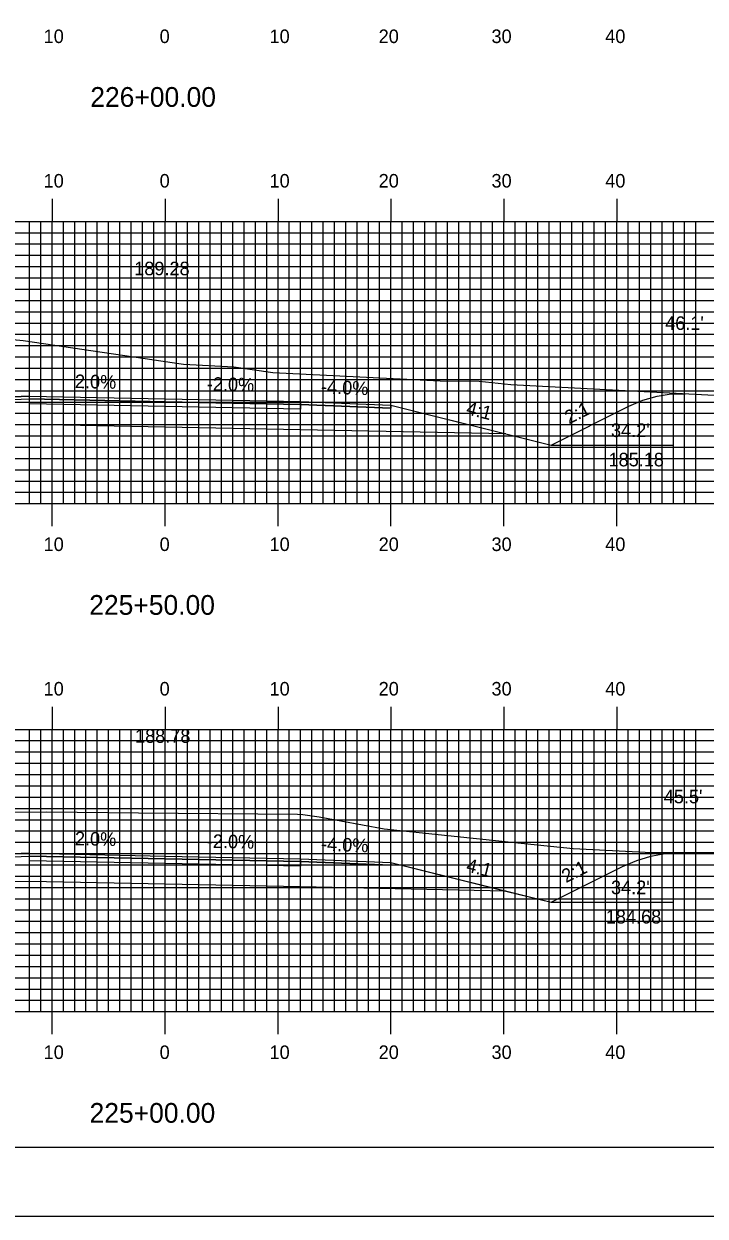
# Model space of a CAD drawing. Extents: x 1798388 to 1798731, y 442591 to 442811.
# Drawn here: x 1798541 to 1798601.3, y 442590.5 to 442696.2 of the extents above; entities that cross this region are included whole.
import ezdxf

# ---------------------------------------------------------------- set-up
doc = ezdxf.new("R2010")
doc.units = 0
for name, color, linetype in [('ANNOTATION', 7, 'Continuous'), ('BORDER', 7, 'Continuous'), ('D_Roadway_Centerline', 7, 'Continuous'), ('D_Roadway_Centerline_Text', 7, 'Continuous'), ('D_Roadway_Edge_Shoulder', 7, 'Continuous'), ('D_Roadway_Edge_TW', 7, 'Continuous'), ('D_Roadway_Pavement', 7, 'Continuous'), ('D_Roadway_SlopeLines', 7, 'Continuous'), ('D_Roadway_SubGrade', 7, 'Continuous'), ('D_Text_Standard', 7, 'Continuous'), ('H_V ANNOTATION', 7, 'Continuous'), ('MAJOR', 7, 'Continuous'), ('MINOR', 7, 'Continuous'), ('PDRAIN', 7, 'Continuous'), ('PLOT BOUNDARY', 7, 'Continuous'), ('S_Roadway_Centerline', 7, 'Continuous')]:
    doc.layers.add(name, color=color, linetype=linetype)

msp = doc.modelspace()

# ---------------------------------------------------------------- linework, layer by layer
at = {"layer": 'BORDER'}
msp.add_lwpolyline([(1798403.87, 442596.67), (1798723.87, 442596.67), (1798723.87, 442806.67), (1798403.87, 442806.67)], close=True, dxfattribs=at)
at = {"layer": 'D_Roadway_Centerline'}
for points in [[(1798501.26, 442666.86), (1798502.51, 442666.89), (1798503.76, 442666.72), (1798505.01, 442666.37), (1798506.26, 442665.84), (1798519.3, 442659.33), (1798523.3, 442660.33), (1798533.47, 442662.87), (1798541.47, 442663.19), (1798553.47, 442662.95), (1798565.47, 442662.71), (1798573.47, 442662.39), (1798583.64, 442659.85), (1798587.64, 442658.85), (1798594.53, 442662.29), (1798595.78, 442662.83), (1798597.03, 442663.19), (1798598.28, 442663.39), (1798599.53, 442663.41)], [(1798502.18, 442626.07), (1798503.43, 442626.02), (1798504.68, 442625.8), (1798505.93, 442625.43), (1798507.18, 442624.88), (1798519.3, 442618.83), (1798523.3, 442619.83), (1798533.47, 442622.37), (1798541.47, 442622.69), (1798553.47, 442622.45), (1798565.47, 442622.21), (1798573.47, 442621.89), (1798583.64, 442619.35), (1798587.64, 442618.35), (1798593.98, 442621.51), (1798595.23, 442622.06), (1798596.48, 442622.45), (1798597.73, 442622.68), (1798598.98, 442622.75)]]:
    msp.add_lwpolyline(points, dxfattribs=at)
at = {"layer": 'D_Roadway_Edge_Shoulder'}
for points in [[(1798541.47, 442663.19), (1798533.47, 442662.87), (1798533.47, 442662.62), (1798541.47, 442662.94)], [(1798565.47, 442662.71), (1798573.47, 442662.39), (1798573.47, 442662.14), (1798565.47, 442662.46)], [(1798541.47, 442622.69), (1798533.47, 442622.37), (1798533.47, 442622.12), (1798541.47, 442622.44)], [(1798565.47, 442622.21), (1798573.47, 442621.89), (1798573.47, 442621.64), (1798565.47, 442621.96)]]:
    msp.add_lwpolyline(points, close=True, dxfattribs=at)
at = {"layer": 'D_Roadway_Edge_TW'}
for points in [[(1798541.47, 442662.94), (1798541.47, 442663.19), (1798553.47, 442662.95), (1798565.47, 442662.71), (1798565.47, 442662.46), (1798553.47, 442662.7)], [(1798541.47, 442622.44), (1798541.47, 442622.69), (1798553.47, 442622.45), (1798565.47, 442622.21), (1798565.47, 442621.96), (1798553.47, 442622.2)]]:
    msp.add_lwpolyline(points, close=True, dxfattribs=at)
at = {"layer": 'D_Roadway_Pavement'}
for points in [[(1798541.47, 442662.52), (1798541.47, 442662.94), (1798553.47, 442662.7), (1798565.47, 442662.46), (1798565.47, 442662.04), (1798553.47, 442662.28)], [(1798541.47, 442622.02), (1798541.47, 442622.44), (1798553.47, 442622.2), (1798565.47, 442621.96), (1798565.47, 442621.54), (1798553.47, 442621.78)]]:
    msp.add_lwpolyline(points, close=True, dxfattribs=at)
at = {"layer": 'D_Roadway_SlopeLines'}
for points in [[(1798587.64, 442658.85), (1798594.53, 442662.29), (1798595.78, 442662.83), (1798597.03, 442663.19), (1798598.28, 442663.39), (1798599.53, 442663.41)], [(1798573.47, 442662.39), (1798587.64, 442658.85)], [(1798587.64, 442618.35), (1798593.98, 442621.51), (1798595.23, 442622.06), (1798596.48, 442622.45), (1798597.73, 442622.68), (1798598.98, 442622.75)], [(1798573.47, 442621.89), (1798587.64, 442618.35)]]:
    msp.add_lwpolyline(points, dxfattribs=at)
at = {"layer": 'D_Roadway_SubGrade'}
for points in [[(1798541.47, 442660.69), (1798523.3, 442660.33), (1798533.47, 442662.87), (1798533.47, 442662.62), (1798541.47, 442662.94), (1798553.47, 442662.7), (1798565.47, 442662.46), (1798573.47, 442662.14), (1798573.47, 442662.39), (1798583.64, 442659.85), (1798565.47, 442660.21), (1798553.47, 442660.45)], [(1798541.47, 442620.19), (1798523.3, 442619.83), (1798533.47, 442622.37), (1798533.47, 442622.12), (1798541.47, 442622.44), (1798553.47, 442622.2), (1798565.47, 442621.96), (1798573.47, 442621.64), (1798573.47, 442621.89), (1798583.64, 442619.35), (1798565.47, 442619.71), (1798553.47, 442619.95)]]:
    msp.add_lwpolyline(points, close=True, dxfattribs=at)
at = {"layer": 'MAJOR'}
for p, q in [((1798543.47, 442680.67), (1798543.47, 442678.67)), ((1798553.47, 442680.67), (1798553.47, 442678.67)), ((1798563.47, 442680.67), (1798563.47, 442678.67)), ((1798573.47, 442680.67), (1798573.47, 442678.67)), ((1798583.47, 442680.67), (1798583.47, 442678.67)), ((1798593.47, 442680.67), (1798593.47, 442678.67)), ((1798413.47, 442678.67), (1798693.47, 442678.67)), ((1798413.47, 442678.67), (1798693.47, 442678.67)), ((1798543.47, 442653.67), (1798543.47, 442678.67)), ((1798553.47, 442653.67), (1798553.47, 442678.67)), ((1798563.47, 442653.67), (1798563.47, 442678.67)), ((1798573.47, 442653.67), (1798573.47, 442678.67)), ((1798583.47, 442653.67), (1798583.47, 442678.67)), ((1798593.47, 442653.67), (1798593.47, 442678.67)), ((1798413.47, 442673.67), (1798693.47, 442673.67)), ((1798413.47, 442668.67), (1798693.47, 442668.67)), ((1798413.47, 442663.67), (1798693.47, 442663.67)), ((1798413.47, 442658.67), (1798693.47, 442658.67)), ((1798413.47, 442653.67), (1798693.47, 442653.67)), ((1798413.47, 442653.67), (1798693.47, 442653.67)), ((1798543.47, 442651.66), (1798543.47, 442653.67)), ((1798553.47, 442651.66), (1798553.47, 442653.67)), ((1798563.47, 442651.66), (1798563.47, 442653.67)), ((1798573.47, 442651.66), (1798573.47, 442653.67)), ((1798583.47, 442651.66), (1798583.47, 442653.67)), ((1798593.47, 442651.66), (1798593.47, 442653.67)), ((1798543.47, 442635.67), (1798543.47, 442633.67)), ((1798553.47, 442635.67), (1798553.47, 442633.67)), ((1798563.47, 442635.67), (1798563.47, 442633.67)), ((1798573.47, 442635.67), (1798573.47, 442633.67)), ((1798583.47, 442635.67), (1798583.47, 442633.67)), ((1798593.47, 442635.67), (1798593.47, 442633.67)), ((1798413.47, 442633.67), (1798693.47, 442633.67)), ((1798413.47, 442633.67), (1798693.47, 442633.67)), ((1798543.47, 442608.67), (1798543.47, 442633.67)), ((1798553.47, 442608.67), (1798553.47, 442633.67)), ((1798563.47, 442608.67), (1798563.47, 442633.67)), ((1798573.47, 442608.67), (1798573.47, 442633.67)), ((1798583.47, 442608.67), (1798583.47, 442633.67)), ((1798593.47, 442608.67), (1798593.47, 442633.67)), ((1798413.47, 442628.67), (1798693.47, 442628.67)), ((1798413.47, 442623.67), (1798693.47, 442623.67)), ((1798413.47, 442618.67), (1798693.47, 442618.67)), ((1798413.47, 442613.67), (1798693.47, 442613.67)), ((1798413.47, 442608.67), (1798693.47, 442608.67)), ((1798413.47, 442608.67), (1798693.47, 442608.67)), ((1798543.47, 442606.66), (1798543.47, 442608.67)), ((1798553.47, 442606.66), (1798553.47, 442608.67)), ((1798563.47, 442606.66), (1798563.47, 442608.67)), ((1798573.47, 442606.66), (1798573.47, 442608.67)), ((1798583.47, 442606.66), (1798583.47, 442608.67)), ((1798593.47, 442606.66), (1798593.47, 442608.67))]:
    msp.add_line(p, q, dxfattribs=at)
at = {"layer": 'MINOR'}
for p, q in [((1798541.47, 442653.67), (1798541.47, 442678.67)), ((1798542.47, 442653.67), (1798542.47, 442678.67)), ((1798544.47, 442653.67), (1798544.47, 442678.67)), ((1798545.47, 442653.67), (1798545.47, 442678.67)), ((1798546.47, 442653.67), (1798546.47, 442678.67)), ((1798547.47, 442653.67), (1798547.47, 442678.67)), ((1798548.47, 442653.67), (1798548.47, 442678.67)), ((1798549.47, 442653.67), (1798549.47, 442678.67)), ((1798550.47, 442653.67), (1798550.47, 442678.67)), ((1798551.47, 442653.67), (1798551.47, 442678.67)), ((1798552.47, 442653.67), (1798552.47, 442678.67)), ((1798554.47, 442653.67), (1798554.47, 442678.67)), ((1798555.47, 442653.67), (1798555.47, 442678.67)), ((1798556.47, 442653.67), (1798556.47, 442678.67)), ((1798557.47, 442653.67), (1798557.47, 442678.67)), ((1798558.47, 442653.67), (1798558.47, 442678.67)), ((1798559.47, 442653.67), (1798559.47, 442678.67)), ((1798560.47, 442653.67), (1798560.47, 442678.67)), ((1798561.47, 442653.67), (1798561.47, 442678.67)), ((1798562.47, 442653.67), (1798562.47, 442678.67)), ((1798564.47, 442653.67), (1798564.47, 442678.67)), ((1798565.47, 442653.67), (1798565.47, 442678.67)), ((1798566.47, 442653.67), (1798566.47, 442678.67)), ((1798567.47, 442653.67), (1798567.47, 442678.67)), ((1798568.47, 442653.67), (1798568.47, 442678.67)), ((1798569.47, 442653.67), (1798569.47, 442678.67)), ((1798570.47, 442653.67), (1798570.47, 442678.67)), ((1798571.47, 442653.67), (1798571.47, 442678.67)), ((1798572.47, 442653.67), (1798572.47, 442678.67)), ((1798574.47, 442653.67), (1798574.47, 442678.67)), ((1798575.47, 442653.67), (1798575.47, 442678.67)), ((1798576.47, 442653.67), (1798576.47, 442678.67)), ((1798577.47, 442653.67), (1798577.47, 442678.67)), ((1798578.47, 442653.67), (1798578.47, 442678.67)), ((1798579.47, 442653.67), (1798579.47, 442678.67)), ((1798580.47, 442653.67), (1798580.47, 442678.67)), ((1798581.47, 442653.67), (1798581.47, 442678.67)), ((1798582.47, 442653.67), (1798582.47, 442678.67)), ((1798584.47, 442653.67), (1798584.47, 442678.67)), ((1798585.47, 442653.67), (1798585.47, 442678.67)), ((1798586.47, 442653.67), (1798586.47, 442678.67)), ((1798587.47, 442653.67), (1798587.47, 442678.67)), ((1798588.47, 442653.67), (1798588.47, 442678.67)), ((1798589.47, 442653.67), (1798589.47, 442678.67)), ((1798590.47, 442653.67), (1798590.47, 442678.67)), ((1798591.47, 442653.67), (1798591.47, 442678.67)), ((1798592.47, 442653.67), (1798592.47, 442678.67)), ((1798594.47, 442653.67), (1798594.47, 442678.67)), ((1798595.47, 442653.67), (1798595.47, 442678.67)), ((1798596.47, 442653.67), (1798596.47, 442678.67)), ((1798597.47, 442653.67), (1798597.47, 442678.67)), ((1798598.47, 442653.67), (1798598.47, 442678.67)), ((1798599.47, 442653.67), (1798599.47, 442678.67)), ((1798600.47, 442653.67), (1798600.47, 442678.67)), ((1798413.47, 442677.67), (1798693.47, 442677.67)), ((1798413.47, 442676.67), (1798693.47, 442676.67)), ((1798413.47, 442675.67), (1798693.47, 442675.67)), ((1798413.47, 442674.67), (1798693.47, 442674.67)), ((1798413.47, 442672.67), (1798693.47, 442672.67)), ((1798413.47, 442671.67), (1798693.47, 442671.67)), ((1798413.47, 442670.67), (1798693.47, 442670.67)), ((1798413.47, 442669.67), (1798693.47, 442669.67)), ((1798413.47, 442667.67), (1798693.47, 442667.67)), ((1798413.47, 442666.67), (1798693.47, 442666.67)), ((1798413.47, 442665.67), (1798693.47, 442665.67)), ((1798413.47, 442664.67), (1798693.47, 442664.67)), ((1798413.47, 442662.67), (1798693.47, 442662.67)), ((1798413.47, 442661.67), (1798693.47, 442661.67)), ((1798413.47, 442660.67), (1798693.47, 442660.67)), ((1798413.47, 442659.67), (1798693.47, 442659.67)), ((1798413.47, 442657.67), (1798693.47, 442657.67)), ((1798413.47, 442656.67), (1798693.47, 442656.67)), ((1798413.47, 442655.67), (1798693.47, 442655.67)), ((1798413.47, 442654.67), (1798693.47, 442654.67)), ((1798541.47, 442608.67), (1798541.47, 442633.67)), ((1798542.47, 442608.67), (1798542.47, 442633.67)), ((1798544.47, 442608.67), (1798544.47, 442633.67)), ((1798545.47, 442608.67), (1798545.47, 442633.67)), ((1798546.47, 442608.67), (1798546.47, 442633.67)), ((1798547.47, 442608.67), (1798547.47, 442633.67)), ((1798548.47, 442608.67), (1798548.47, 442633.67)), ((1798549.47, 442608.67), (1798549.47, 442633.67)), ((1798550.47, 442608.67), (1798550.47, 442633.67)), ((1798551.47, 442608.67), (1798551.47, 442633.67)), ((1798552.47, 442608.67), (1798552.47, 442633.67)), ((1798554.47, 442608.67), (1798554.47, 442633.67)), ((1798555.47, 442608.67), (1798555.47, 442633.67)), ((1798556.47, 442608.67), (1798556.47, 442633.67)), ((1798557.47, 442608.67), (1798557.47, 442633.67)), ((1798558.47, 442608.67), (1798558.47, 442633.67)), ((1798559.47, 442608.67), (1798559.47, 442633.67)), ((1798560.47, 442608.67), (1798560.47, 442633.67)), ((1798561.47, 442608.67), (1798561.47, 442633.67)), ((1798562.47, 442608.67), (1798562.47, 442633.67)), ((1798564.47, 442608.67), (1798564.47, 442633.67)), ((1798565.47, 442608.67), (1798565.47, 442633.67)), ((1798566.47, 442608.67), (1798566.47, 442633.67)), ((1798567.47, 442608.67), (1798567.47, 442633.67)), ((1798568.47, 442608.67), (1798568.47, 442633.67)), ((1798569.47, 442608.67), (1798569.47, 442633.67)), ((1798570.47, 442608.67), (1798570.47, 442633.67)), ((1798571.47, 442608.67), (1798571.47, 442633.67)), ((1798572.47, 442608.67), (1798572.47, 442633.67)), ((1798574.47, 442608.67), (1798574.47, 442633.67)), ((1798575.47, 442608.67), (1798575.47, 442633.67)), ((1798576.47, 442608.67), (1798576.47, 442633.67)), ((1798577.47, 442608.67), (1798577.47, 442633.67)), ((1798578.47, 442608.67), (1798578.47, 442633.67)), ((1798579.47, 442608.67), (1798579.47, 442633.67)), ((1798580.47, 442608.67), (1798580.47, 442633.67)), ((1798581.47, 442608.67), (1798581.47, 442633.67)), ((1798582.47, 442608.67), (1798582.47, 442633.67)), ((1798584.47, 442608.67), (1798584.47, 442633.67)), ((1798585.47, 442608.67), (1798585.47, 442633.67)), ((1798586.47, 442608.67), (1798586.47, 442633.67)), ((1798587.47, 442608.67), (1798587.47, 442633.67)), ((1798588.47, 442608.67), (1798588.47, 442633.67)), ((1798589.47, 442608.67), (1798589.47, 442633.67)), ((1798590.47, 442608.67), (1798590.47, 442633.67)), ((1798591.47, 442608.67), (1798591.47, 442633.67)), ((1798592.47, 442608.67), (1798592.47, 442633.67)), ((1798594.47, 442608.67), (1798594.47, 442633.67)), ((1798595.47, 442608.67), (1798595.47, 442633.67)), ((1798596.47, 442608.67), (1798596.47, 442633.67)), ((1798597.47, 442608.67), (1798597.47, 442633.67)), ((1798598.47, 442608.67), (1798598.47, 442633.67)), ((1798599.47, 442608.67), (1798599.47, 442633.67)), ((1798600.47, 442608.67), (1798600.47, 442633.67)), ((1798413.47, 442632.67), (1798693.47, 442632.67)), ((1798413.47, 442631.67), (1798693.47, 442631.67)), ((1798413.47, 442630.67), (1798693.47, 442630.67)), ((1798413.47, 442629.67), (1798693.47, 442629.67)), ((1798413.47, 442627.67), (1798693.47, 442627.67)), ((1798413.47, 442626.67), (1798693.47, 442626.67)), ((1798413.47, 442625.67), (1798693.47, 442625.67)), ((1798413.47, 442624.67), (1798693.47, 442624.67)), ((1798413.47, 442622.67), (1798693.47, 442622.67)), ((1798413.47, 442621.67), (1798693.47, 442621.67)), ((1798413.47, 442620.67), (1798693.47, 442620.67)), ((1798413.47, 442619.67), (1798693.47, 442619.67)), ((1798413.47, 442617.67), (1798693.47, 442617.67)), ((1798413.47, 442616.67), (1798693.47, 442616.67)), ((1798413.47, 442615.67), (1798693.47, 442615.67)), ((1798413.47, 442614.67), (1798693.47, 442614.67)), ((1798413.47, 442612.67), (1798693.47, 442612.67)), ((1798413.47, 442611.67), (1798693.47, 442611.67)), ((1798413.47, 442610.67), (1798693.47, 442610.67)), ((1798413.47, 442609.67), (1798693.47, 442609.67))]:
    msp.add_line(p, q, dxfattribs=at)
at = {"layer": 'PDRAIN'}
for p, q in [((1798587.64, 442658.85), (1798598.42, 442658.85)), ((1798587.64, 442618.35), (1798598.42, 442618.35))]:
    msp.add_line(p, q, dxfattribs=at)
at = {"layer": 'PLOT BOUNDARY'}
msp.add_lwpolyline([(1798387.68, 442590.55), (1798727.68, 442590.55), (1798727.68, 442810.55), (1798387.68, 442810.55)], close=True, dxfattribs=at)
at = {"layer": 'S_Roadway_Centerline'}
for points in [[(1798492.98, 442666.44), (1798497.86, 442666.51), (1798497.88, 442666.56), (1798507.35, 442667.42), (1798518.91, 442668.88), (1798525.56, 442669.39), (1798528.75, 442669.26), (1798535.39, 442668.65), (1798540.9, 442668.12), (1798555.11, 442666.02), (1798559.56, 442665.78), (1798563.02, 442665.3), (1798577.82, 442664.54), (1798581.28, 442664.51), (1798584.09, 442664.22), (1798602.09, 442663.27)], [(1798494.03, 442625.84), (1798495.29, 442625.9), (1798495.76, 442625.92), (1798496.16, 442625.93), (1798497.61, 442625.96), (1798512.51, 442626.32), (1798519.04, 442626.25), (1798521.23, 442626.25), (1798522.5, 442626.3), (1798523.66, 442626.34), (1798524.2, 442626.37), (1798527.61, 442626.4), (1798530.56, 442626.41), (1798531, 442626.34), (1798542.97, 442626.36), (1798551.12, 442626.28), (1798565.19, 442626.16), (1798565.66, 442626.14), (1798567.1, 442625.92), (1798572.88, 442624.87), (1798584.14, 442623.68), (1798589.61, 442623.12), (1798596.58, 442622.76), (1798602.18, 442622.75)]]:
    msp.add_lwpolyline(points, dxfattribs=at)

# ---------------------------------------------------------------- texts
at = {"layer": 'ANNOTATION'}
for s, rotation, p in [('2.0%', 358.8542, (1798545.48, 442663.91)), ('-2.0%', 358.8542, (1798557.16, 442663.68)), ('-4.0%', 357.7094, (1798567.26, 442663.44)), ('4:1', 345.9638, (1798580.06, 442661.6)), ('2:1', 26.5651, (1798589.23, 442660.68)), ('2.0%', 358.8542, (1798545.48, 442623.41)), ('-2.0%', 358.8542, (1798557.16, 442623.18)), ('-4.0%', 357.7094, (1798567.26, 442622.94)), ('4:1', 345.9638, (1798580.06, 442621.1)), ('2:1', 26.5651, (1798588.96, 442620.04))]:
    msp.add_text(s, height=1.2, rotation=rotation, dxfattribs=at).set_placement(p)
for s, p in [("34.2'", (1798592.95, 442659.57)), ('185.18', (1798592.73, 442656.97)), ("34.2'", (1798592.95, 442619.07)), ('184.68', (1798592.49, 442616.47))]:
    msp.add_text(s, height=1.2, dxfattribs=at).set_placement(p)
at = {"layer": 'D_Roadway_Centerline'}
for s, p in [('C', (1798553.47, 442662.95)), ('L', (1798553.47, 442662.94)), ('C', (1798553.47, 442622.45)), ('L', (1798553.47, 442622.44))]:
    msp.add_text(s, height=0.0146, dxfattribs=at).set_placement(p)
at = {"layer": 'D_Roadway_Centerline_Text'}
for s, p in [('189.28', (1798550.74, 442673.9)), ('188.78', (1798550.81, 442632.48))]:
    msp.add_text(s, height=1.2, dxfattribs=at).set_placement(p)
at = {"layer": 'D_Text_Standard'}
for s, p in [("46.1'", (1798597.74, 442669.06)), ("45.5'", (1798597.62, 442627.12))]:
    msp.add_text(s, height=1.2, dxfattribs=at).set_placement(p)
at = {"layer": 'H_V ANNOTATION'}
for s, height, p in [('10', 1.2, (1798542.72, 442694.47)), ('0', 1.2, (1798552.99, 442694.47)), ('10', 1.2, (1798562.72, 442694.47)), ('20', 1.2, (1798572.38, 442694.47)), ('30', 1.2, (1798582.37, 442694.47)), ('40', 1.2, (1798592.44, 442694.47)), ('226+00.00', 1.75, (1798546.85, 442688.82)), ('10', 1.2, (1798542.72, 442681.67)), ('0', 1.2, (1798552.99, 442681.67)), ('10', 1.2, (1798562.72, 442681.67)), ('20', 1.2, (1798572.38, 442681.67)), ('30', 1.2, (1798582.37, 442681.67)), ('40', 1.2, (1798592.44, 442681.67)), ('10', 1.2, (1798542.72, 442649.47)), ('0', 1.2, (1798552.99, 442649.47)), ('10', 1.2, (1798562.72, 442649.47)), ('20', 1.2, (1798572.38, 442649.47)), ('30', 1.2, (1798582.37, 442649.47)), ('40', 1.2, (1798592.44, 442649.47)), ('225+50.00', 1.75, (1798546.76, 442643.82)), ('10', 1.2, (1798542.72, 442636.67)), ('0', 1.2, (1798552.99, 442636.67)), ('10', 1.2, (1798562.72, 442636.67)), ('20', 1.2, (1798572.38, 442636.67)), ('30', 1.2, (1798582.37, 442636.67)), ('40', 1.2, (1798592.44, 442636.67)), ('10', 1.2, (1798542.72, 442604.47)), ('0', 1.2, (1798552.99, 442604.47)), ('10', 1.2, (1798562.72, 442604.47)), ('20', 1.2, (1798572.38, 442604.47)), ('30', 1.2, (1798582.37, 442604.47)), ('40', 1.2, (1798592.44, 442604.47)), ('225+00.00', 1.75, (1798546.79, 442598.82))]:
    msp.add_text(s, height=height, dxfattribs=at).set_placement(p)

doc.saveas('drawing.dxf')
